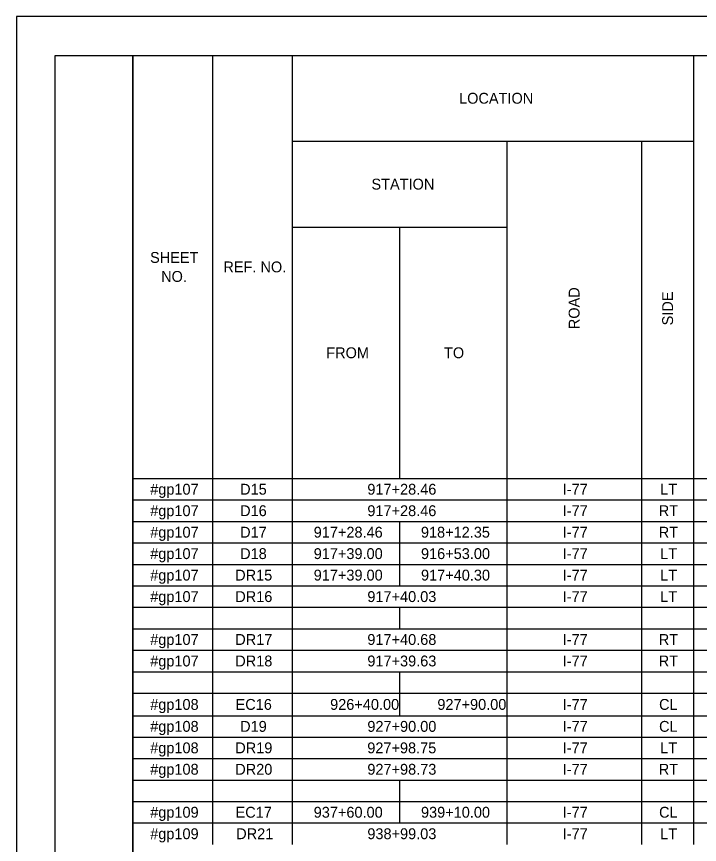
# Model space of a CAD drawing. Extents: x 0.2 to 34.2, y 0 to 22.
# Drawn here: x 0.19 to 9, y 11.35 to 22.03 of the extents above; entities that cross this region are included whole.
import ezdxf

# ---------------------------------------------------------------- set-up
doc = ezdxf.new("R2010")
doc.units = 0
for name, color, linetype in [('SH_Border', 7, 'Continuous'), ('SH_Cut_Line', 7, 'Continuous'), ('SH_Text', 7, 'Continuous')]:
    doc.layers.add(name, color=color, linetype=linetype)

msp = doc.modelspace()

# ---------------------------------------------------------------- linework, layer by layer
at = {"layer": 'SH_Border'}
for points in [[(0.692, 21.525), (1.692, 21.525), (1.692, 0.525), (0.692, 0.525)], [(1.692, 21.525), (33.692, 21.525), (33.692, 0.525), (1.692, 0.525)]]:
    msp.add_lwpolyline(points, close=True, dxfattribs=at)
at = {"layer": 'SH_Cut_Line'}
msp.add_lwpolyline([(0.192, 0.025), (34.192, 0.025), (34.192, 22.025), (0.192, 22.025)], close=True, dxfattribs=at)
at = {"layer": 'SH_Text'}
for p, q in [((1.692, 21.525), (8.254, 21.525)), ((1.692, 21.525), (1.692, 21.249)), ((2.72, 21.525), (2.72, 21.249)), ((3.748, 21.525), (3.748, 21.249)), ((8.254, 21.525), (13.643, 21.525)), ((8.926, 21.525), (8.926, 21.249)), ((1.692, 21.249), (1.692, 20.972)), ((2.72, 21.249), (2.72, 20.972)), ((3.748, 21.249), (3.748, 20.972)), ((8.926, 21.249), (8.926, 20.972)), ((1.692, 20.972), (1.692, 20.695)), ((2.72, 20.972), (2.72, 20.695)), ((3.748, 20.972), (3.748, 20.695)), ((8.926, 20.972), (8.926, 20.695)), ((1.692, 20.695), (1.692, 20.418)), ((2.72, 20.695), (2.72, 20.418)), ((3.748, 20.695), (3.748, 20.418)), ((8.926, 20.695), (8.926, 20.418)), ((1.692, 20.418), (1.692, 20.142)), ((2.72, 20.418), (2.72, 20.142)), ((3.748, 20.418), (8.254, 20.418)), ((3.748, 20.418), (3.748, 20.142)), ((6.515, 20.418), (6.515, 20.142)), ((8.254, 20.418), (8.926, 20.418)), ((8.254, 20.418), (8.254, 20.142)), ((8.926, 20.418), (8.926, 20.142)), ((1.692, 20.142), (1.692, 19.865)), ((2.72, 20.142), (2.72, 19.865)), ((3.748, 20.142), (3.748, 19.865)), ((6.515, 20.142), (6.515, 19.865)), ((8.254, 20.142), (8.254, 19.865)), ((8.926, 20.142), (8.926, 19.865)), ((1.692, 19.865), (1.692, 19.588)), ((2.72, 19.865), (2.72, 19.588)), ((3.748, 19.865), (3.748, 19.588)), ((6.515, 19.865), (6.515, 19.588)), ((8.254, 19.865), (8.254, 19.588)), ((8.926, 19.865), (8.926, 19.588)), ((1.692, 19.588), (1.692, 19.312)), ((2.72, 19.588), (2.72, 19.312)), ((3.748, 19.588), (3.748, 19.312)), ((6.515, 19.588), (6.515, 19.312)), ((8.254, 19.588), (8.254, 19.312)), ((8.926, 19.588), (8.926, 19.312)), ((1.692, 19.312), (1.692, 19.035)), ((2.72, 19.312), (2.72, 19.035)), ((3.748, 19.312), (6.515, 19.312)), ((3.748, 19.312), (3.748, 19.035)), ((5.131, 19.312), (5.131, 19.035)), ((6.515, 19.312), (6.515, 19.035)), ((8.254, 19.312), (8.254, 19.035)), ((8.926, 19.312), (8.926, 19.035)), ((1.692, 19.035), (1.692, 18.758)), ((2.72, 19.035), (2.72, 18.758)), ((3.748, 19.035), (3.748, 18.758)), ((5.131, 19.035), (5.131, 18.758)), ((6.515, 19.035), (6.515, 18.758)), ((8.254, 19.035), (8.254, 18.758)), ((8.926, 19.035), (8.926, 18.758)), ((1.692, 18.758), (1.692, 18.482)), ((2.72, 18.758), (2.72, 18.482)), ((3.748, 18.758), (3.748, 18.482)), ((5.131, 18.758), (5.131, 18.482)), ((6.515, 18.758), (6.515, 18.482)), ((8.254, 18.758), (8.254, 18.482)), ((8.926, 18.758), (8.926, 18.482)), ((1.692, 18.482), (1.692, 18.205)), ((2.72, 18.482), (2.72, 18.205)), ((3.748, 18.482), (3.748, 18.205)), ((5.131, 18.482), (5.131, 18.205)), ((6.515, 18.482), (6.515, 18.205)), ((8.254, 18.482), (8.254, 18.205)), ((8.926, 18.482), (8.926, 18.205)), ((1.692, 18.205), (1.692, 16.347)), ((2.72, 18.205), (2.72, 16.347)), ((3.748, 18.205), (3.748, 16.347)), ((5.131, 18.205), (5.131, 16.347)), ((6.515, 18.205), (6.515, 16.347)), ((8.254, 18.205), (8.254, 16.347)), ((8.926, 18.205), (8.926, 16.347)), ((1.692, 16.347), (1.692, 16.07)), ((2.72, 16.347), (2.72, 16.07)), ((3.748, 16.347), (3.748, 16.07)), ((5.131, 16.347), (5.131, 16.07)), ((6.515, 16.347), (6.515, 16.07)), ((8.254, 16.347), (8.254, 16.07)), ((8.926, 16.347), (8.926, 16.07)), ((1.692, 16.07), (8.254, 16.07)), ((1.692, 16.07), (1.692, 15.794)), ((2.72, 16.07), (2.72, 15.794)), ((3.748, 16.07), (3.748, 15.794)), ((6.515, 16.07), (6.515, 15.794)), ((8.254, 16.07), (13.643, 16.07)), ((8.254, 16.07), (8.254, 15.794)), ((8.926, 16.07), (8.926, 15.794)), ((1.692, 15.794), (8.254, 15.794)), ((1.692, 15.794), (1.692, 15.517)), ((2.72, 15.794), (2.72, 15.517)), ((3.748, 15.794), (3.748, 15.517)), ((6.515, 15.794), (6.515, 15.517)), ((8.254, 15.794), (13.643, 15.794)), ((8.254, 15.794), (8.254, 15.517)), ((8.926, 15.794), (8.926, 15.517)), ((1.692, 15.517), (8.254, 15.517)), ((1.692, 15.517), (1.692, 15.24)), ((2.72, 15.517), (2.72, 15.24)), ((3.748, 15.517), (3.748, 15.24)), ((5.131, 15.517), (5.131, 15.24)), ((6.515, 15.517), (6.515, 15.24)), ((8.254, 15.517), (13.643, 15.517)), ((8.254, 15.517), (8.254, 15.24)), ((8.926, 15.517), (8.926, 15.24)), ((1.692, 15.24), (8.254, 15.24)), ((1.692, 15.24), (1.692, 14.963)), ((2.72, 15.24), (2.72, 14.963)), ((3.748, 15.24), (3.748, 14.963)), ((5.131, 15.24), (5.131, 14.963)), ((6.515, 15.24), (6.515, 14.963)), ((8.254, 15.24), (13.643, 15.24)), ((8.254, 15.24), (8.254, 14.963)), ((8.926, 15.24), (8.926, 14.963)), ((1.692, 14.963), (8.254, 14.963)), ((1.692, 14.963), (1.692, 14.687)), ((2.72, 14.963), (2.72, 14.687)), ((3.748, 14.963), (3.748, 14.687)), ((5.131, 14.963), (5.131, 14.687)), ((6.515, 14.963), (6.515, 14.687)), ((8.254, 14.963), (13.643, 14.963)), ((8.254, 14.963), (8.254, 14.687)), ((8.926, 14.963), (8.926, 14.687)), ((1.692, 14.687), (8.254, 14.687)), ((1.692, 14.687), (1.692, 14.41)), ((2.72, 14.687), (2.72, 14.41)), ((3.748, 14.687), (3.748, 14.41)), ((6.515, 14.687), (6.515, 14.41)), ((8.254, 14.687), (13.643, 14.687)), ((8.254, 14.687), (8.254, 14.41)), ((8.926, 14.687), (8.926, 14.41)), ((1.692, 14.41), (8.254, 14.41)), ((1.692, 14.41), (1.692, 14.133)), ((2.72, 14.41), (2.72, 14.133)), ((3.748, 14.41), (3.748, 14.133)), ((5.131, 14.41), (5.131, 14.133)), ((6.515, 14.41), (6.515, 14.133)), ((8.254, 14.41), (13.643, 14.41)), ((8.254, 14.41), (8.254, 14.133)), ((8.926, 14.41), (8.926, 14.133)), ((1.692, 14.133), (8.254, 14.133)), ((1.692, 14.133), (1.692, 13.857)), ((2.72, 14.133), (2.72, 13.857)), ((3.748, 14.133), (3.748, 13.857)), ((6.515, 14.133), (6.515, 13.857)), ((8.254, 14.133), (13.643, 14.133)), ((8.254, 14.133), (8.254, 13.857)), ((8.926, 14.133), (8.926, 13.857)), ((1.692, 13.857), (8.254, 13.857)), ((1.692, 13.857), (1.692, 13.58)), ((2.72, 13.857), (2.72, 13.58)), ((3.748, 13.857), (3.748, 13.58)), ((6.515, 13.857), (6.515, 13.58)), ((8.254, 13.857), (13.643, 13.857)), ((8.254, 13.857), (8.254, 13.58)), ((8.926, 13.857), (8.926, 13.58)), ((1.692, 13.58), (8.254, 13.58)), ((1.692, 13.58), (1.692, 13.303)), ((2.72, 13.58), (2.72, 13.303)), ((3.748, 13.58), (3.748, 13.303)), ((5.131, 13.58), (5.131, 13.303)), ((6.515, 13.58), (6.515, 13.303)), ((8.254, 13.58), (13.643, 13.58)), ((8.254, 13.58), (8.254, 13.303)), ((8.926, 13.58), (8.926, 13.303)), ((1.692, 13.303), (8.254, 13.303)), ((1.692, 13.303), (1.692, 13.013)), ((2.72, 13.303), (2.72, 13.013)), ((3.748, 13.303), (3.748, 13.013)), ((5.131, 13.303), (5.131, 13.013)), ((6.515, 13.303), (6.515, 13.013)), ((8.254, 13.303), (13.643, 13.303)), ((8.254, 13.303), (8.254, 13.013)), ((8.926, 13.303), (8.926, 13.013)), ((1.692, 13.013), (8.254, 13.013)), ((1.692, 13.013), (1.692, 12.737)), ((2.72, 13.013), (2.72, 12.737)), ((3.748, 13.013), (3.748, 12.737)), ((6.515, 13.013), (6.515, 12.737)), ((8.254, 13.013), (13.643, 13.013)), ((8.254, 13.013), (8.254, 12.737)), ((8.926, 13.013), (8.926, 12.737)), ((1.692, 12.737), (8.254, 12.737)), ((1.692, 12.737), (1.692, 12.46)), ((2.72, 12.737), (2.72, 12.46)), ((3.748, 12.737), (3.748, 12.46)), ((6.515, 12.737), (6.515, 12.46)), ((8.254, 12.737), (13.643, 12.737)), ((8.254, 12.737), (8.254, 12.46)), ((8.926, 12.737), (8.926, 12.46)), ((1.692, 12.46), (8.254, 12.46)), ((1.692, 12.46), (1.692, 12.183)), ((2.72, 12.46), (2.72, 12.183)), ((3.748, 12.46), (3.748, 12.183)), ((6.515, 12.46), (6.515, 12.183)), ((8.254, 12.46), (13.643, 12.46)), ((8.254, 12.46), (8.254, 12.183)), ((8.926, 12.46), (8.926, 12.183)), ((1.692, 12.183), (8.254, 12.183)), ((1.692, 12.183), (1.692, 11.906)), ((2.72, 12.183), (2.72, 11.906)), ((3.748, 12.183), (3.748, 11.906)), ((5.131, 12.183), (5.131, 11.906)), ((6.515, 12.183), (6.515, 11.906)), ((8.254, 12.183), (13.643, 12.183)), ((8.254, 12.183), (8.254, 11.906)), ((8.926, 12.183), (8.926, 11.906)), ((1.692, 11.906), (8.254, 11.906)), ((1.692, 11.906), (1.692, 11.63)), ((2.72, 11.906), (2.72, 11.63)), ((3.748, 11.906), (3.748, 11.63)), ((5.131, 11.906), (5.131, 11.63)), ((6.515, 11.906), (6.515, 11.63)), ((8.254, 11.906), (13.643, 11.906)), ((8.254, 11.906), (8.254, 11.63)), ((8.926, 11.906), (8.926, 11.63)), ((1.692, 11.63), (8.254, 11.63)), ((1.692, 11.63), (1.692, 11.353)), ((2.72, 11.63), (2.72, 11.353)), ((3.748, 11.63), (3.748, 11.353)), ((6.515, 11.63), (6.515, 11.353)), ((8.254, 11.63), (13.643, 11.63)), ((8.254, 11.63), (8.254, 11.353)), ((8.926, 11.63), (8.926, 11.353))]:
    msp.add_line(p, q, dxfattribs=at)

# ---------------------------------------------------------------- texts
for s, p in [('LOCATION', (5.9, 20.902)), ('STATION', (4.77, 19.795)), ('SHEET', (1.914, 18.85)), ('REF. NO.', (2.86, 18.728)), ('NO.', (2.057, 18.605)), ('FROM', (4.187, 17.621)), ('TO', (5.706, 17.621)), ('#gp107', (1.916, 15.862)), ('D15', (3.076, 15.862)), ('917+28.46', (4.717, 15.862)), ('I-77', (7.237, 15.862)), ('LT', (8.495, 15.862)), ('#gp107', (1.916, 15.585)), ('D16', (3.076, 15.585)), ('917+28.46', (4.717, 15.585)), ('I-77', (7.237, 15.585)), ('RT', (8.476, 15.585)), ('#gp107', (1.916, 15.308)), ('D17', (3.076, 15.308)), ('917+28.46', (4.025, 15.308)), ('918+12.35', (5.408, 15.308)), ('I-77', (7.237, 15.308)), ('RT', (8.476, 15.308)), ('#gp107', (1.916, 15.032)), ('D18', (3.076, 15.032)), ('917+39.00', (4.025, 15.032)), ('916+53.00', (5.409, 15.032)), ('I-77', (7.237, 15.032)), ('LT', (8.495, 15.032)), ('#gp107', (1.916, 14.755)), ('DR15', (3.012, 14.755)), ('917+39.00', (4.025, 14.755)), ('917+40.30', (5.409, 14.755)), ('I-77', (7.237, 14.755)), ('LT', (8.495, 14.755)), ('#gp107', (1.916, 14.478)), ('DR16', (3.013, 14.478)), ('917+40.03', (4.717, 14.478)), ('I-77', (7.237, 14.478)), ('LT', (8.495, 14.478)), ('#gp107', (1.916, 13.925)), ('DR17', (3.013, 13.925)), ('917+40.68', (4.717, 13.925)), ('I-77', (7.237, 13.925)), ('RT', (8.476, 13.925)), ('#gp107', (1.916, 13.648)), ('DR18', (3.013, 13.648)), ('917+39.63', (4.717, 13.648)), ('I-77', (7.237, 13.648)), ('RT', (8.476, 13.648)), ('#gp108', (1.916, 13.088)), ('EC16', (3.017, 13.088)), ('926+40.00', (4.237, 13.088)), ('927+90.00', (5.62, 13.088)), ('I-77', (7.237, 13.088)), ('CL', (8.48, 13.088)), ('#gp108', (1.916, 12.805)), ('D19', (3.076, 12.805)), ('927+90.00', (4.717, 12.805)), ('I-77', (7.237, 12.805)), ('CL', (8.48, 12.805)), ('#gp108', (1.916, 12.528)), ('DR19', (3.013, 12.528)), ('927+98.75', (4.716, 12.528)), ('I-77', (7.237, 12.528)), ('LT', (8.495, 12.528)), ('#gp108', (1.916, 12.252)), ('DR20', (3.013, 12.252)), ('927+98.73', (4.717, 12.252)), ('I-77', (7.237, 12.252)), ('RT', (8.476, 12.252)), ('#gp109', (1.916, 11.698)), ('EC17', (3.017, 11.698)), ('937+60.00', (4.025, 11.698)), ('939+10.00', (5.409, 11.698)), ('I-77', (7.237, 11.698)), ('CL', (8.48, 11.698)), ('#gp109', (1.916, 11.421)), ('DR21', (3.025, 11.421)), ('938+99.03', (4.717, 11.421)), ('I-77', (7.237, 11.421)), ('LT', (8.495, 11.421))]:
    msp.add_text(s, height=0.14, dxfattribs=at).set_placement(p)
for s, p in [('ROAD', (7.454, 17.995)), ('SIDE', (8.66, 18.044))]:
    msp.add_text(s, height=0.14, rotation=90, dxfattribs=at).set_placement(p)

doc.saveas('drawing.dxf')
